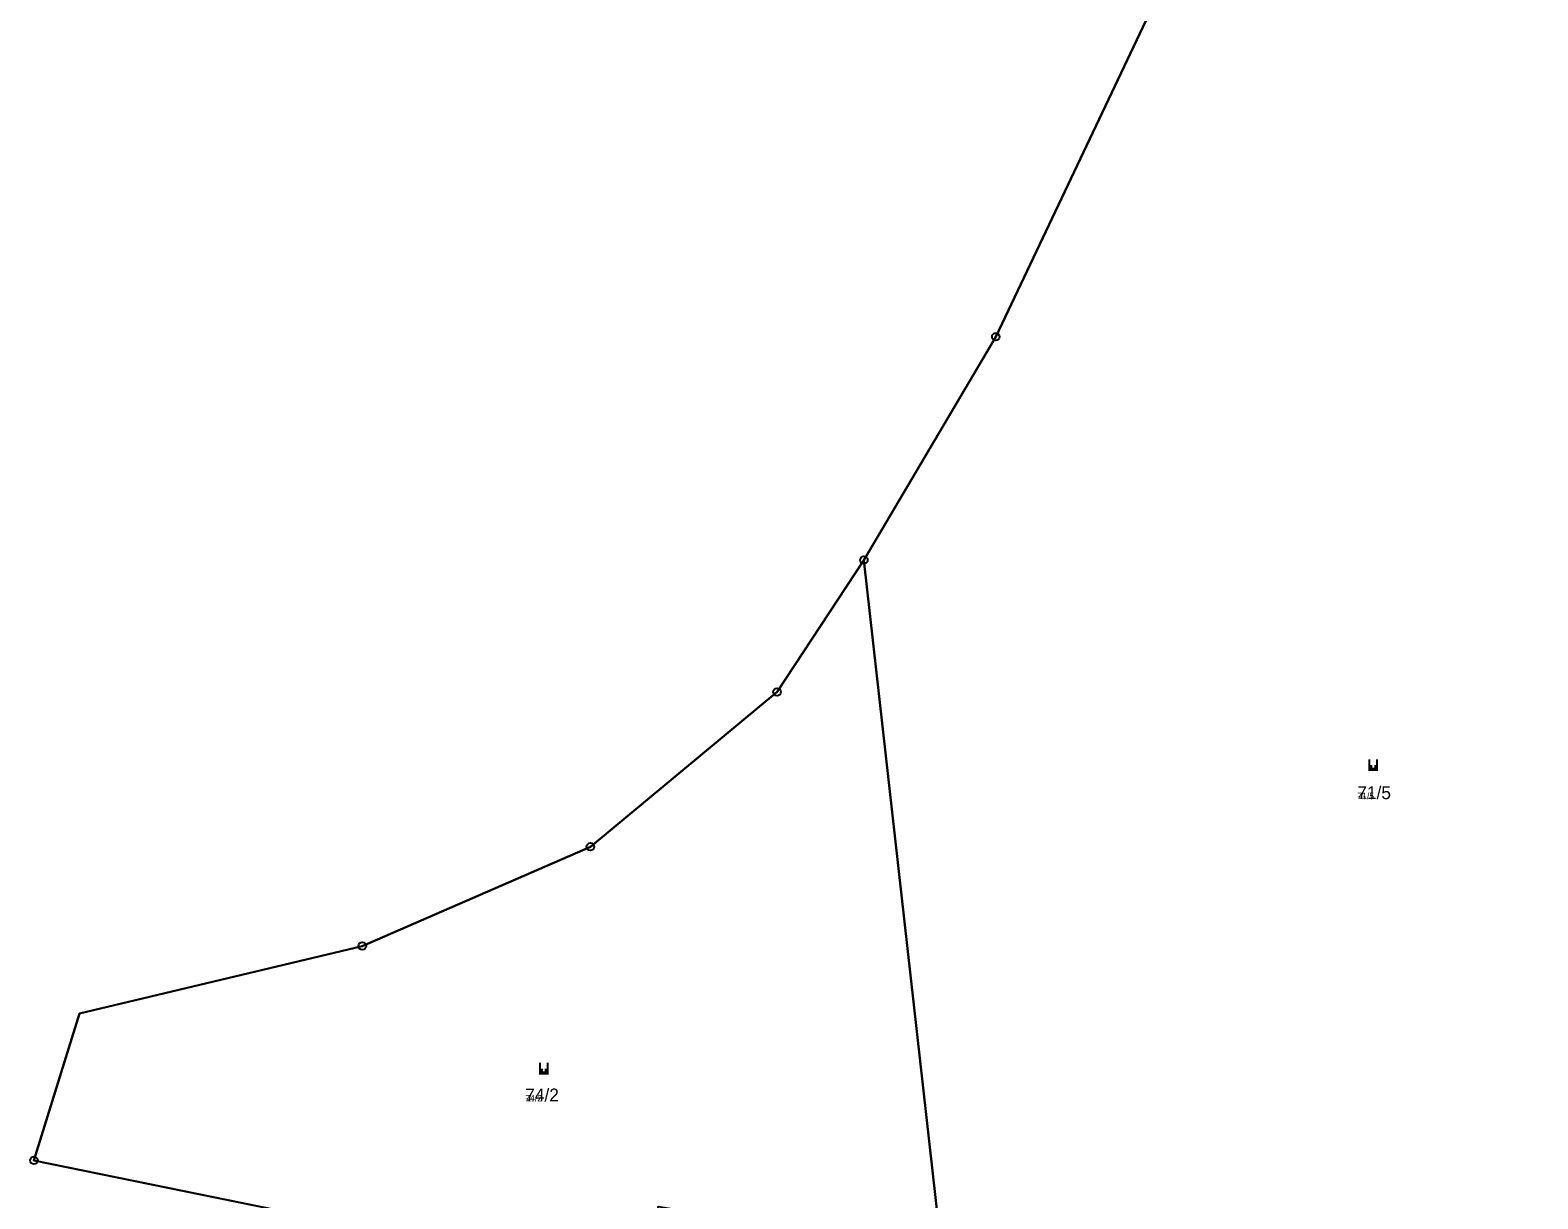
# Model space of a CAD drawing. Extents: x -759873 to -758487, y -975024 to -973516.
# Drawn here: x -759872.5 to -759674.3, y -974042.3 to -973888.7 of the extents above; entities that cross this region are included whole.
import ezdxf

# ---------------------------------------------------------------- set-up
doc = ezdxf.new("R2010")
doc.units = 0
for name, color, linetype in [('KAT_01_hranice KU', 7, 'Continuous'), ('KAT_02_hranice parcel', 7, 'Continuous'), ('KAT_03_1000_čísla parcelní', 7, 'Continuous'), ('KAT_03_250_čísla parcelní', 7, 'Continuous'), ('KAT_03_500_čísla parcelní', 7, 'Continuous'), ('KAT_05_1000_značky kultur', 7, 'Continuous'), ('KAT_05_250_značky kultur', 7, 'Continuous'), ('KAT_05_500_značky kultur', 7, 'Continuous'), ('KAT_11_značky bodu BP', 7, 'Continuous'), ('KAT_14_plocha_pozemek', 7, 'Continuous')]:
    doc.layers.add(name, color=color, linetype=linetype)

msp = doc.modelspace()

# ---------------------------------------------------------------- linework, layer by layer
at = {"layer": 'KAT_01_hranice KU'}
msp.add_lwpolyline([(-759409.89, -973735.02), (-759469.84, -973753.89), (-759524.16, -973754.8), (-759548.45, -973765.63), (-759553.38, -973767.83), (-759560.5, -973771), (-759594, -973804.35), (-759642.86, -973817.27), (-759646.4, -973820.05), (-759673.37, -973834.52), (-759675.2, -973835.5), (-759686.95, -973842.38), (-759689.8, -973844.05), (-759704.1, -973854.15), (-759721.15, -973878.47), (-759722.5, -973880.4), (-759745.55, -973929), (-759762.9, -973958.35), (-759774.3, -973975.7), (-759798.85, -973996.05), (-759828.85, -974009.1), (-759866.03, -974017.98), (-759872.01, -974037.29), (-759792.52, -974053.5)], dxfattribs=at)
at = {"layer": 'KAT_02_hranice parcel'}
for p, q in [((-759774.3, -973975.7), (-759762.9, -973958.35)), ((-759762.9, -973958.35), (-759752.64, -974049.58)), ((-759872.01, -974037.29), (-759866.03, -974017.98)), ((-759792.52, -974053.5), (-759872.01, -974037.29))]:
    msp.add_line(p, q, dxfattribs=at)
for points in [[(-759762.9, -973958.35), (-759745.55, -973929), (-759722.5, -973880.4)], [(-759866.03, -974017.98), (-759828.85, -974009.1), (-759798.85, -973996.05), (-759774.3, -973975.7)]]:
    msp.add_lwpolyline(points, dxfattribs=at)
at = {"layer": 'KAT_05_1000_značky kultur'}
for p, q in [((-759696.4, -973986.06), (-759696.4, -973984.56)), ((-759695.4, -973986.06), (-759695.4, -973984.56)), ((-759805.45, -974025.98), (-759805.45, -974024.48)), ((-759804.45, -974025.98), (-759804.45, -974024.48))]:
    msp.add_line(p, q, dxfattribs=at)
at = {"layer": 'KAT_05_250_značky kultur'}
for p, q in [((-759696.02, -973986.06), (-759696.02, -973985.69)), ((-759695.77, -973986.06), (-759695.77, -973985.69)), ((-759805.07, -974025.98), (-759805.07, -974025.6)), ((-759804.82, -974025.98), (-759804.82, -974025.6))]:
    msp.add_line(p, q, dxfattribs=at)
at = {"layer": 'KAT_05_500_značky kultur'}
for p, q in [((-759696.15, -973986.06), (-759696.15, -973985.31)), ((-759695.65, -973986.06), (-759695.65, -973985.31)), ((-759805.2, -974025.98), (-759805.2, -974025.23)), ((-759804.7, -974025.98), (-759804.7, -974025.23))]:
    msp.add_line(p, q, dxfattribs=at)
at = {"layer": 'KAT_11_značky bodu BP'}
for centre, radius in [((-759745.55, -973929), 0.5), ((-759745.55, -973929), 0.0303), ((-759762.9, -973958.35), 0.5), ((-759762.9, -973958.35), 0.0303), ((-759774.3, -973975.7), 0.5), ((-759774.3, -973975.7), 0.0303), ((-759798.85, -973996.05), 0.5), ((-759798.85, -973996.05), 0.0303), ((-759828.85, -974009.1), 0.5), ((-759828.85, -974009.1), 0.0303), ((-759872.01, -974037.29), 0.5), ((-759872.01, -974037.29), 0.0303)]:
    msp.add_circle(centre, radius, dxfattribs=at)
at = {"layer": 'KAT_14_plocha_pozemek'}
msp.add_lwpolyline([(-759595.2, -974059.1), (-759593.11, -974016.5), (-759601.09, -974012.98), (-759614.83, -974009.59), (-759625.66, -973989.4), (-759648.01, -973964.72), (-759665.96, -973928.2), (-759670.51, -973914.46), (-759671.07, -973906.7), (-759666.51, -973891.74), (-759658.11, -973874), (-759660.11, -973862.2), (-759673.37, -973834.52), (-759675.2, -973835.5), (-759686.95, -973842.38), (-759689.8, -973844.05), (-759704.1, -973854.15), (-759721.15, -973878.47), (-759722.5, -973880.4), (-759745.55, -973929), (-759762.9, -973958.35), (-759752.64, -974049.58)], dxfattribs=at)
msp.add_lwpolyline([(-759792.52, -974053.5), (-759789.91, -974043.34), (-759752.64, -974049.58), (-759762.9, -973958.35), (-759774.3, -973975.7), (-759798.85, -973996.05), (-759828.85, -974009.1), (-759866.03, -974017.98), (-759872.01, -974037.29)], close=True, dxfattribs=at)

# ---------------------------------------------------------------- texts
at = {"layer": 'KAT_03_1000_čísla parcelní'}
for s, p in [('71/5', (-759698.02, -973989.79)), ('74/2', (-759807.42, -974029.54))]:
    msp.add_text(s, height=1.7, dxfattribs=at).set_placement(p)
at = {"layer": 'KAT_03_250_čísla parcelní'}
for s, p in [('71/5', (-759698.02, -973989.79)), ('74/2', (-759807.42, -974029.54))]:
    msp.add_text(s, height=0.425, dxfattribs=at).set_placement(p)
at = {"layer": 'KAT_03_500_čísla parcelní'}
for s, p in [('71/5', (-759698.02, -973989.79)), ('74/2', (-759807.42, -974029.54))]:
    msp.add_text(s, height=0.85, dxfattribs=at).set_placement(p)

doc.saveas('drawing.dxf')
